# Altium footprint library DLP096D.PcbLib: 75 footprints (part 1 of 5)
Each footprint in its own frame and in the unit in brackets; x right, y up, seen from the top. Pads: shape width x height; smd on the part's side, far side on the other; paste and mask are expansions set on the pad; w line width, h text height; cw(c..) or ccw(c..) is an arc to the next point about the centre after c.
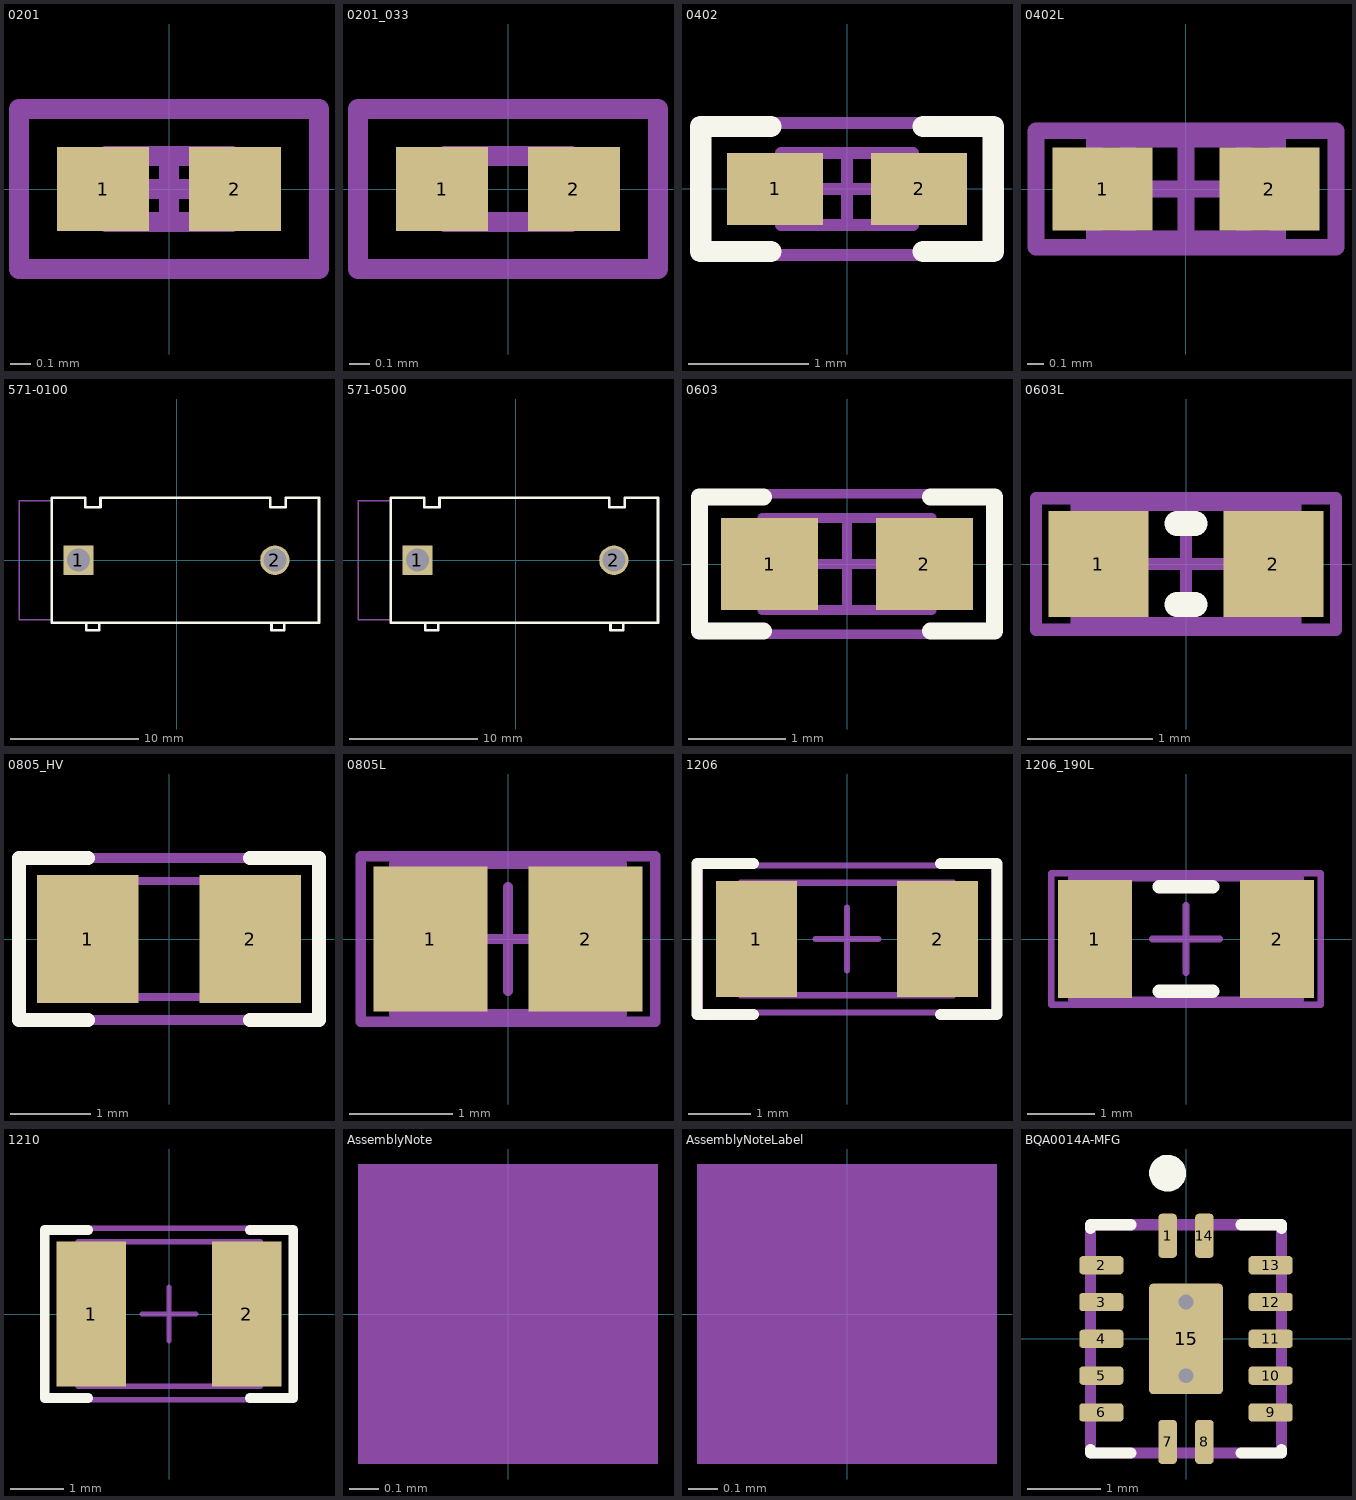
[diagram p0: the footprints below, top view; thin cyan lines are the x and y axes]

## 0201 [mm] "Data from Kemet datasheet CC101_COM dated 7/28/11"
height 0.26
pads (2):
  rect 0.46x0.42 smd mask+0.048: 1(-0.33,0) 2(0.33,0)
Mechanical 5:
  lines w0.1: -0.75,-0.4 0.75,-0.4 0.75,0.4 -0.75,0.4 -0.75,-0.4
  text ".Designator" at -0.66,-0.178 h0.36
Mechanical 13:
  lines w0.1: -0.215,-0.165 -0.215,0.165 ; 0.215,-0.165 0.215,0.165 ; -0.315,-0.165 -0.315,0.165 0.315,0.165 0.315,-0.165 -0.315,-0.165
Mechanical 15:
  lines w0.1: -0.165,0 0.165,0 ; 0,-0.165 0,0.165 ; -0.75,-0.4 -0.75,0.4 0.75,0.4 0.75,-0.4 -0.75,-0.4
3D body: height 0.26, standoff 0, extent -0.314,-0.164 -0.216,0.164
3D body: height 0.26, standoff 0, extent -0.214,-0.164 0.214,0.164
3D body: height 0.26, standoff 0, extent 0.216,-0.164 0.314,0.164

## 0201_033 [mm] "SMD, 2-Leads, Height 0.33mm"
height 0.33
pads (2):
  rect 0.46x0.42 smd mask+0.048: 1(-0.33,0) 2(0.33,0)
Mechanical 5:
  lines w0.1: -0.75,-0.4 -0.75,0.4 0.75,0.4 0.75,-0.4 -0.75,-0.4
  text ".Designator" at -0.66,-0.178 h0.36
Mechanical 13:
  lines w0.1: -0.215,-0.165 -0.215,0.165 ; 0.215,-0.165 0.215,0.165 ; -0.315,-0.165 0.315,-0.165 0.315,0.165 -0.315,0.165 -0.315,-0.165
3D body: height 0.33, standoff 0, extent 0.216,-0.164 0.314,0.164
3D body: height 0.33, standoff 0, extent -0.214,-0.164 0.214,0.164
3D body: height 0.33, standoff 0, extent -0.314,-0.164 -0.216,0.164

## 0402 [mm] "0402 from SM-752 data"
height 0.6
pads (2):
  rect 0.8x0.6 smd: 1(-0.6,0) 2(0.6,0)
Top Overlay:
  lines w0.178: -0.635,-0.521 -1.219,-0.521 -1.219,0.521 -0.635,0.521 ; 0.635,-0.521 1.219,-0.521 1.219,0.521 0.635,0.521
Mechanical 5:
  lines w0.1: -1.25,-0.55 1.25,-0.55 1.25,0.55 -1.25,0.55 -1.25,-0.55
  text ".Designator" at -1.117,-0.305 h0.61
Mechanical 13:
  lines w0.1: -0.35,-0.3 -0.35,0.3 ; 0.35,-0.3 0.35,0.3 ; -0.55,-0.3 -0.55,0.3 0.55,0.3 0.55,-0.3 -0.55,-0.3
Mechanical 15:
  lines w0.1: -0.3,0 0.3,0 ; 0,-0.3 0,0.3 ; -1.25,-0.55 -1.25,0.55 1.25,0.55 1.25,-0.55 -1.25,-0.55
3D body: height 0.6, standoff 0, extent -0.549,-0.299 -0.351,0.299
3D body: height 0.6, standoff 0, extent -0.349,-0.299 0.349,0.299
3D body: height 0.6, standoff 0, extent 0.351,-0.299 0.549,0.299

## 0402L [mm] "0402 from SM-752 data"
height 0.6
pads (2):
  rect 0.6x0.5 smd: 1(-0.5,0) 2(0.5,0)
Mechanical 5:
  lines w0.1: -0.9,-0.35 0.9,-0.35 0.9,0.35 -0.9,0.35 -0.9,-0.35
  text ".Designator" at -0.775,-0.225 h0.43
Mechanical 13:
  lines w0.1: -0.35,-0.3 -0.35,0.3 ; 0.35,-0.3 0.35,0.3 ; -0.55,-0.3 -0.55,0.3 0.55,0.3 0.55,-0.3 -0.55,-0.3
Mechanical 15:
  lines w0.1: -0.3,0 0.3,0 ; 0,-0.3 0,0.3 ; -0.9,-0.35 -0.9,0.35 0.9,0.35 0.9,-0.35 -0.9,-0.35
3D body: height 0.6, standoff 0, extent -0.549,-0.299 -0.351,0.299
3D body: height 0.6, standoff 0, extent -0.349,-0.299 0.349,0.299
3D body: height 0.6, standoff 0, extent 0.351,-0.299 0.549,0.299

## 571-0100 [mm] "Deltron Emcon recommended land pattern 2003-10-13"
height 12.4
pads (2):
  rect 2.3x2.3 hole 1.8: 1(-7.65,0)
  round 2.3 hole 1.8: 2(7.65,0)
Top Overlay:
  lines w0.2: -7.035,-4.875 -9.745,-4.875 -9.745,-3.375 -9.745,3.375 -9.745,4.875 -7.135,4.875 -7.135,4.125 -5.935,4.125 -5.935,4.875 7.285,4.875 7.285,4.125 8.485,4.125 8.485,4.875 11.085,4.875 11.085,3.375 11.085,-3.375 11.085,-4.875 8.385,-4.875 ; -7.035,-4.875 -6.035,-4.875 ; -7.035,-4.875 -7.035,-5.475 -6.035,-5.475 -6.035,-4.875 ; -6.035,-4.875 7.385,-4.875 ; 7.385,-4.875 8.385,-4.875 ; 7.385,-4.875 7.385,-5.475 8.385,-5.475 8.385,-4.875
Mechanical 5:
  lines w0.1: -9.745,-4.635 -12.285,-4.635 -12.285,4.635 -9.745,4.635 ; -7.035,-4.875 -7.035,-5.475 -6.035,-5.475 -6.035,-4.875 ; -7.035,-4.875 -6.035,-4.875 ; -7.035,-4.875 -9.745,-4.875 -9.745,-3.375 -9.745,3.375 -9.745,4.875 -7.135,4.875 -7.135,4.125 -5.935,4.125 -5.935,4.875 7.285,4.875 7.285,4.125 8.485,4.125 8.485,4.875 11.085,4.875 11.085,3.375 11.085,-3.375 11.085,-4.875 8.385,-4.875 ; -6.035,-4.875 7.385,-4.875 ; 7.385,-4.875 7.385,-5.475 8.385,-5.475 8.385,-4.875 ; 7.385,-4.875 8.385,-4.875
  text ".Designator" at -1.3,-0.7 h1.52
3D body "Deltron_571-0100.stp": height 12.41, standoff -5.49, extent -12.285,-5.475 11.085,4.875

## 571-0500 [mm] "Deltron Emcon recommended land pattern 2003-10-13"
height 12.4
pads (2):
  rect 2.3x2.3 hole 1.8: 1(-7.65,0)
  round 2.3 hole 1.8: 2(7.65,0)
Top Overlay:
  lines w0.2: -7.035,-4.875 -9.745,-4.875 -9.745,-3.375 -9.745,3.375 -9.745,4.875 -7.135,4.875 -7.135,4.125 -5.935,4.125 -5.935,4.875 7.285,4.875 7.285,4.125 8.485,4.125 8.485,4.875 11.085,4.875 11.085,3.375 11.085,-3.375 11.085,-4.875 8.385,-4.875 ; -7.035,-4.875 -6.035,-4.875 ; -7.035,-4.875 -7.035,-5.475 -6.035,-5.475 -6.035,-4.875 ; -6.035,-4.875 7.385,-4.875 ; 7.385,-4.875 8.385,-4.875 ; 7.385,-4.875 7.385,-5.475 8.385,-5.475 8.385,-4.875
Mechanical 5:
  lines w0.1: -9.745,-4.635 -12.285,-4.635 -12.285,4.635 -9.745,4.635 ; -7.035,-4.875 -7.035,-5.475 -6.035,-5.475 -6.035,-4.875 ; -7.035,-4.875 -6.035,-4.875 ; -7.035,-4.875 -9.745,-4.875 -9.745,-3.375 -9.745,3.375 -9.745,4.875 -7.135,4.875 -7.135,4.125 -5.935,4.125 -5.935,4.875 7.285,4.875 7.285,4.125 8.485,4.125 8.485,4.875 11.085,4.875 11.085,3.375 11.085,-3.375 11.085,-4.875 8.385,-4.875 ; -6.035,-4.875 7.385,-4.875 ; 7.385,-4.875 7.385,-5.475 8.385,-5.475 8.385,-4.875 ; 7.385,-4.875 8.385,-4.875
  text ".Designator" at -1.3,-0.7 h1.52
3D body "Deltron_571-0500.stp": height 12.41, standoff -5.49, extent -12.285,-5.475 11.085,4.875

## 0603 [mm] "0603 from SM-752 data"
height 1
pads (2):
  rect 1x0.95 smd: 1(-0.8,0) 2(0.8,0)
Top Overlay:
  lines w0.178: -0.864,-0.691 -1.524,-0.691 -1.524,0.693 -0.864,0.693 ; 0.864,-0.691 1.524,-0.691 1.524,0.693 0.864,0.693
Mechanical 5:
  lines w0.1: -1.55,-0.725 -1.55,0.725 1.55,0.725 1.55,-0.725 -1.55,-0.725
  text ".Designator" at -1.397,-0.381 h0.76
Mechanical 13:
  lines w0.1: -0.55,-0.475 -0.55,0.475 ; 0.55,-0.475 0.55,0.475 ; -0.875,-0.475 0.875,-0.475 0.875,0.475 -0.875,0.475 -0.875,-0.475
Mechanical 15:
  lines w0.1: -0.475,0 0.475,0 ; 0,-0.475 0,0.475 ; -1.55,-0.725 1.55,-0.725 1.55,0.725 -1.55,0.725 -1.55,-0.725
3D body: height 1, standoff 0, extent -0.874,-0.474 -0.551,0.474
3D body: height 1, standoff 0, extent -0.549,-0.474 0.549,0.474
3D body: height 1, standoff 0, extent 0.551,-0.474 0.874,0.474

## 0603L [mm] "0603 from SM-752 data"
height 1
pads (2):
  rect 0.8x0.85 smd: 1(-0.7,0) 2(0.7,0)
Top Overlay:
  lines w0.2: -0.071,-0.325 0.071,-0.325 ; -0.071,0.325 0.071,0.325
Mechanical 5:
  lines w0.1: -1.2,-0.525 -1.2,0.525 1.2,0.525 1.2,-0.525 -1.2,-0.525
  text ".Designator" at -1.05,-0.275 h0.56
Mechanical 13:
  lines w0.1: -0.55,-0.475 -0.55,0.475 ; 0.55,-0.475 0.55,0.475 ; -0.875,-0.475 -0.875,0.475 0.875,0.475 0.875,-0.475 -0.875,-0.475
Mechanical 15:
  lines w0.1: -0.475,0 0.475,0 ; 0,-0.475 0,0.475 ; -1.2,-0.525 1.2,-0.525 1.2,0.525 -1.2,0.525 -1.2,-0.525
3D body: height 1, standoff 0, extent 0.551,-0.474 0.874,0.474
3D body: height 1, standoff 0, extent -0.549,-0.474 0.549,0.474
3D body: height 1, standoff 0, extent -0.874,-0.474 -0.551,0.474

## 0805_HV [mil] "0805 with 30mil clearance between pads"
height 57.09
pads (2):
  rect 50x63 smd: 1(-40,0) 2(40,0)
Top Overlay:
  lines w7: -40,-40 -74,-40 -74,0 -74,40 -40,40 ; 40,-40 74,-40 74,0 74,40 40,40
Mechanical 5:
  lines w5: -74,-40 -74,40 74,40 74,-40 -74,-40
  text ".Designator" at -64,-17 h35
Mechanical 13:
  lines w3.94: -25.59,-28.54 -25.59,28.54 ; 25.59,-28.54 25.59,28.54 ; -43.31,-28.54 -43.31,28.54 43.31,28.54 43.31,-28.54 -43.31,-28.54
3D body: height 57.09, standoff 0, extent 25.61,-28.52 43.29,28.52
3D body: height 57.09, standoff 0, extent -25.57,-28.52 25.57,28.52
3D body: height 57.09, standoff 0, extent -43.29,-28.52 -25.61,28.52

## 0805L [mm] "0805 from SM-752 data"
height 1.45
pads (2):
  rect 1.1x1.4 smd: 1(-0.75,0) 2(0.75,0)
Mechanical 5:
  lines w0.1: -1.425,-0.8 1.425,-0.8 1.425,0.8 -1.425,0.8 -1.425,-0.8
  text ".Designator" at -1.2,-0.325 h0.64
Mechanical 13:
  lines w0.1: -0.65,-0.725 -0.65,0.725 ; 0.65,-0.725 0.65,0.725 ; -1.1,-0.725 -1.1,0.725 1.1,0.725 1.1,-0.725 -1.1,-0.725
Mechanical 15:
  lines w0.1: -0.5,0 0.5,0 ; 0,-0.5 0,0.5 ; -1.425,-0.8 -1.425,0.8 1.425,0.8 1.425,-0.8 -1.425,-0.8
3D body: height 1.45, standoff 0, extent 0.651,-0.724 1.099,0.724
3D body: height 1.45, standoff 0, extent -0.649,-0.724 0.649,0.724
3D body: height 1.45, standoff 0, extent -1.099,-0.724 -0.651,0.724

## 1206 [mm] "1206 from SM-752 data"
height 1.35
pads (2):
  rect 1.3x1.85 smd: 1(-1.45,0) 2(1.45,0)
Top Overlay:
  lines w0.178: -1.5,-1.21 -2.4,-1.21 -2.4,1.21 -1.5,1.21 ; 1.5,-1.21 2.4,-1.21 2.4,1.21 1.5,1.21
Mechanical 5:
  lines w0.1: -1.7,-0.9 -1.7,0.9 1.7,0.9 1.7,-0.9 -1.7,-0.9
  text ".Designator" at -1.475,-0.4 h0.81
Mechanical 13:
  lines w0.1: -1.2,-0.9 -1.2,0.9 ; 1.2,-0.9 1.2,0.9 ; -1.7,-0.9 -1.7,0.9 1.7,0.9 1.7,-0.9 -1.7,-0.9
Mechanical 15:
  lines w0.1: -0.5,0 0.5,0 ; 0,-0.5 0,0.5 ; -2.35,-1.175 -2.35,1.175 2.35,1.175 2.35,-1.175 -2.35,-1.175
3D body: height 1.35, standoff 0, extent 1.201,-0.899 1.699,0.899
3D body: height 1.35, standoff 0, extent -1.199,-0.899 1.199,0.899
3D body: height 1.35, standoff 0, extent -1.699,-0.899 -1.201,0.899

## 1206_190L [mm] "1206_190"
height 1.9
pads (2):
  rect 1.1x1.75 smd: 1(-1.35,0) 2(1.35,0)
Top Overlay:
  lines w0.2: -0.4,-0.775 0.4,-0.775 ; -0.4,0.775 0.4,0.775
Mechanical 5:
  lines w0.1: -1.7,-0.9 -1.7,0.9 1.7,0.9 1.7,-0.9 -1.7,-0.9
  text ".Designator" at -1.475,-0.4 h0.81
Mechanical 15:
  lines w0.1: -0.5,0 0.5,0 ; 0,-0.5 0,0.5 ; -2,-0.975 -2,0.975 2,0.975 2,-0.975 -2,-0.975
3D body: height 1.9, standoff 0, extent 1.301,-0.949 1.75,0.95
3D body: height 1.9, standoff 0, extent -1.299,-0.949 1.3,0.95
3D body: height 1.9, standoff 0, extent -1.749,-0.949 -1.3,0.95

## 1210 [mm] "1210 from SM-752 data"
height 1.35
pads (2):
  rect 1.3x2.7 smd: 1(-1.45,0) 2(1.45,0)
Top Overlay:
  lines w0.178: -1.511,-1.568 -2.316,-1.568 -2.316,1.568 -1.511,1.568 ; 1.511,-1.568 2.316,-1.568 2.316,1.568 1.511,1.568
Mechanical 5:
  lines w0.1: -1.7,-1.35 1.7,-1.35 1.7,1.35 -1.7,1.35 -1.7,-1.35
  text ".Designator" at -1.4,-0.375 h0.76
Mechanical 13:
  lines w0.1: -1.2,-1.35 -1.2,1.35 ; 1.2,-1.35 1.2,1.35 ; -1.7,-1.35 -1.7,1.35 1.7,1.35 1.7,-1.35 -1.7,-1.35
Mechanical 15:
  lines w0.1: -0.5,0 0.5,0 ; 0,-0.5 0,0.5 ; -2.35,-1.6 -2.35,1.6 2.35,1.6 2.35,-1.6 -2.35,-1.6
3D body: height 1.35, standoff 0, extent -1.699,-1.349 -1.201,1.349
3D body: height 1.35, standoff 0, extent -1.199,-1.349 1.199,1.349
3D body: height 1.35, standoff 0, extent 1.201,-1.349 1.699,1.349

## AssemblyNote [mm] "Assembly Note"
Mechanical 5:
  rectangle: -0.508,-0.508 0.508,0.508
  text ".Designator" at -4.191,-0.508 h1.02
  text ".Comment" at 1.143,-0.508 h1.02

## AssemblyNoteLabel [mm] "Assembly Note for PCB Labels"
Mechanical 5:
  rectangle: -0.508,-0.508 0.508,0.508
  text "Install label in silkscreened box after final wash.  Text shall be 8 pt font.  Text shall be per the Label Table in the PDF schematic." at 1.143,-0.508 h1.02
  text ".Designator" at -4.191,-0.508 h1.02

## BQA0014A-MFG [mm]
pads (15):
  rrect40% 0.25x0.6 smd paste+0 mask+0: 1(-0.25,1.4) 7(-0.25,-1.4) 8(0.25,-1.4) 14(0.25,1.4)
  rrect40% 0.6x0.25 smd paste+0 mask+0: 2(-1.15,1) 3(-1.15,0.5) 4(-1.15,0) 5(-1.15,-0.5) 6(-1.15,-1) 9(1.15,-1) 10(1.15,-0.5) 11(1.15,0) 12(1.15,0.5) 13(1.15,1)
  rrect10% 1x1.5 smd paste-1000 mask+0: 15(0,0)
via 0,0.5 diameter 0.5 hole 0.2
via 0,-0.5 diameter 0.5 hole 0.2
Top Overlay:
  circle w0.25: c-0.25,2.25 r0.125
  lines w0.15: -1.3,-1.5 -1.3,-1.55 -0.75,-1.55 ; -1.3,1.5 -1.3,1.55 -0.75,1.55 ; 0.75,-1.55 1.3,-1.55 1.3,-1.5 ; 0.75,1.55 1.3,1.55 1.3,1.5
Top Paste:
  region: 0.425,-0.69 -0.425,-0.69 -0.435,-0.69 -0.453,-0.682 -0.467,-0.668 -0.475,-0.65 -0.475,-0.64 -0.475,0.64 -0.475,0.65 -0.467,0.668 -0.453,0.682 -0.435,0.69 -0.425,0.69 0.425,0.69 0.435,0.69 0.453,0.682 0.467,0.668 0.475,0.65 0.475,0.64 0.475,-0.64 0.475,-0.65 0.467,-0.668 0.453,-0.682 0.435,-0.69
Mechanical 5:
  lines w0.15: -1.3,-1.55 -1.3,1.55 1.3,1.55 1.3,-1.55 -1.3,-1.55
  text ".Designator" at 0,0 h0.5
3D body "IC_TXU0104BQAR_WQFN14.STEP": height 0.25, standoff 0, extent -1.55,-1.8 1.55,1.8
